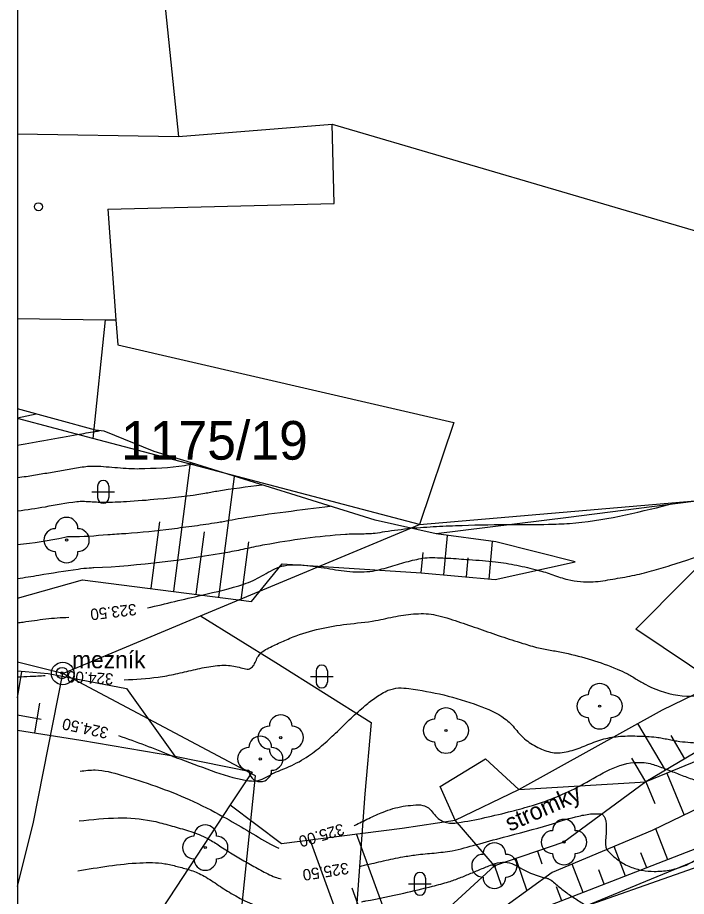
# Model space of a CAD drawing. Extents: x -564037 to -563827, y -1163561 to -1163412.
# Drawn here: x -564036.51 to -564007.08, y -1163509.03 to -1163470.35 of the extents above; entities that cross this region are included whole.
import ezdxf

# ---------------------------------------------------------------- set-up
doc = ezdxf.new("R2010")
doc.units = 0
for name, color, linetype in [('_rám PH2 a PH4', 7, 'Continuous'), ('Definiční bod kú', 7, 'Continuous'), ('Hranice parcel', 7, 'Continuous'), ('Parcelní čísla', 7, 'Continuous'), ('Vnitřní kresba', 7, 'Continuous'), ('Vrstva 14', 7, 'Continuous'), ('Vrstva 21', 7, 'Continuous'), ('Vrstva 22', 7, 'Continuous'), ('Vrstva 24', 7, 'Continuous'), ('Vrstva 25', 7, 'Continuous'), ('Vrstva 26', 7, 'Continuous'), ('Vrstva 41', 7, 'Continuous'), ('Vrstva 48', 7, 'Continuous'), ('Značky bodu BP', 7, 'Continuous'), ('Značky budov', 7, 'Continuous')]:
    doc.layers.add(name, color=color, linetype=linetype)

msp = doc.modelspace()

# ---------------------------------------------------------------- linework, layer by layer
at = {"layer": '_rám PH2 a PH4'}
msp.add_line((-564036.505, -1163412.494), (-564036.505, -1163560.994), dxfattribs=at)
at = {"layer": 'Definiční bod kú'}
msp.add_lwpolyline([(-564036.505, -1163529.976), (-564035.88, -1163528.59), (-564032.62, -1163523.46), (-564027.5, -1163518.53), (-564023.88, -1163515.79), (-564019.18, -1163512.89), (-564014.48, -1163510.5), (-564004.65, -1163507.04), (-563996.46, -1163502.51), (-563993.72, -1163500.97), (-563990.58, -1163498.69), (-563987.18, -1163495.32), (-563983.19, -1163487.81), (-563979.82, -1163480.39), (-563975.55, -1163472.37), (-563971.76, -1163466.68), (-563970.57, -1163458.32), (-563969.42, -1163449.87), (-563967.93, -1163441.99), (-563966.12, -1163434.66), (-563963.95, -1163427.04), (-563963.19, -1163422.98), (-563961.48, -1163418.93), (-563957.126, -1163412.494)], dxfattribs=at)
at = {"layer": 'Hranice parcel'}
for p, q in [((-564032.65, -1163483.65), (-564033.19, -1163488.88)), ((-564033.19, -1163488.88), (-564036.505, -1163488.003)), ((-564018.83, -1163492.67), (-564033.19, -1163488.88)), ((-564018.83, -1163492.67), (-564003.59, -1163491.36)), ((-564028.46, -1163496.69), (-564018.83, -1163492.67)), ((-564034.52, -1163499.22), (-564028.46, -1163496.69))]:
    msp.add_line(p, q, dxfattribs=at)
for points in [[(-563978.16, -1163460.35), (-563977.81, -1163470.18), (-563986.9, -1163494.46), (-563994.41, -1163501.54), (-564003.29, -1163506.07), (-564021.9, -1163513.74)], [(-564036.505, -1163475.472), (-564029.42, -1163475.59), (-564022.66, -1163475.05), (-564001.49, -1163481.27)], [(-564036.505, -1163483.596), (-564032.65, -1163483.65)], [(-564032.65, -1163483.65), (-564032.18, -1163483.66), (-564032.1, -1163484.76), (-564017.32, -1163488.18), (-564018.83, -1163492.67)], [(-564028.46, -1163496.69), (-564025.15, -1163498.74), (-564020.95, -1163501.38), (-564021.23, -1163504.52), (-564021.9, -1163513.74)], [(-564034.52, -1163499.22), (-564036.505, -1163498.716)], [(-564036.505, -1163508.595), (-564035.8, -1163505.76), (-564034.52, -1163499.22)], [(-564033.84, -1163535.6), (-564027.54, -1163518.14), (-564026.04, -1163503.72), (-564034.52, -1163499.22)]]:
    msp.add_lwpolyline(points, dxfattribs=at)
at = {"layer": 'Vnitřní kresba'}
for p, q in [((-564030.92, -1163461.24), (-564029.42, -1163475.59)), ((-564022.58, -1163478.54), (-564022.66, -1163475.05)), ((-564032.54, -1163478.78), (-564022.58, -1163478.54)), ((-564032.54, -1163478.78), (-564032.18, -1163483.66))]:
    msp.add_line(p, q, dxfattribs=at)
at = {"layer": 'Vrstva 14'}
for points in [[(-563978.09, -1163460.32), (-563977.36, -1163462.71), (-563977.84, -1163465.15), (-563976.09, -1163465.55), (-563974.34, -1163466.75), (-563974.1, -1163467.69), (-563974.4, -1163469.44), (-563976.73, -1163469.93), (-563977.88, -1163469.51), (-563978.75, -1163470.09), (-563979.22, -1163471.2), (-563981.47, -1163479.57), (-563983.82, -1163487.72), (-563987.7, -1163494.99), (-563990.79, -1163498.34), (-563994.06, -1163500.55), (-563996.65, -1163502.12), (-564005.13, -1163506.34), (-564014.58, -1163510.01)], [(-564033.08, -1163488.51), (-564036.505, -1163487.58)], [(-564032.69, -1163488.56), (-564033.08, -1163488.51)], [(-564005.7, -1163491.6), (-564006.2, -1163491.58), (-564012.27, -1163492.36), (-564018.09, -1163493.08), (-564020.78, -1163492.48), (-564028.85, -1163489.95), (-564030.49, -1163489.45), (-564032.69, -1163488.56)], [(-564027.15, -1163505), (-564024.9, -1163506.7), (-564019.59, -1163506.03), (-564017.25, -1163505.67), (-564014.46, -1163504.32), (-564008.13, -1163500.82), (-564005.74, -1163499.66), (-563997.05, -1163495.87), (-563995.48, -1163492.66)], [(-564011.97, -1163494.31), (-564015.47, -1163493.43), (-564018.09, -1163493.08)], [(-564036.505, -1163495.911), (-564033.65, -1163495.1), (-564026.22, -1163496.05), (-564024.87, -1163494.39), (-564018.75, -1163494.79), (-564015.5, -1163495.09), (-564011.97, -1163494.31)], [(-563994.18, -1163495.16), (-563996.51, -1163497.07), (-563999.3, -1163498.37), (-564001.37, -1163499.69), (-564002.8, -1163500.4), (-564008.87, -1163503.99)], [(-563993.16, -1163495.9), (-563996.19, -1163498.22), (-563998.5, -1163499.46), (-564002.25, -1163501.27), (-564008.87, -1163503.99)], [(-563991.13, -1163497.04), (-563995.37, -1163499.78), (-563998.83, -1163501.38), (-564002.12, -1163503), (-564008.59, -1163506.13), (-564012.99, -1163507.98), (-564015.01, -1163509.44), (-564017.68, -1163509.66)], [(-564036.505, -1163499.099), (-564035.16, -1163499.22), (-564031.72, -1163499.88), (-564029.59, -1163502.86)], [(-564036.505, -1163501.708), (-564033.72, -1163502.16), (-564029.59, -1163502.86), (-564026.18, -1163503.55), (-564027.15, -1163505), (-564030.15, -1163509.57), (-564034.03, -1163515.15), (-564036.505, -1163518.922)], [(-564008.87, -1163503.99), (-564012.47, -1163506.64), (-564015.53, -1163507.68), (-564017.68, -1163509.66), (-564019.48, -1163510.39), (-564022.84, -1163511.62), (-564024.26, -1163512.8), (-564027.09, -1163514.75), (-564027.62, -1163513.07), (-564028.61, -1163510.34), (-564030.15, -1163509.57)]]:
    msp.add_lwpolyline(points, dxfattribs=at)
at = {"layer": 'Vrstva 21'}
for points in [[(-564005.74, -1163499.66), (-564009.31, -1163497.27), (-564004.92, -1163492.86)], [(-564017.25, -1163505.67), (-564017.92, -1163504.2), (-564015.92, -1163502.97), (-564014.46, -1163504.32)], [(-564014.46, -1163504.32), (-564008.87, -1163503.99)], [(-564015.53, -1163507.68), (-564017.25, -1163505.67)]]:
    msp.add_lwpolyline(points, dxfattribs=at)
at = {"layer": 'Vrstva 22'}
for centre in [(-564034.35, -1163493.35), (-564010.9, -1163500.66), (-564017.66, -1163501.73), (-564024.93, -1163502.04), (-564025.83, -1163502.98), (-564012.47, -1163506.64), (-564028.25, -1163506.88), (-564015.53, -1163507.68)]:
    msp.add_circle(centre, 0.05, dxfattribs=at)
for centre, start, end in [((-564034.35, -1163492.85), 0, 180), ((-564034.85, -1163493.35), 90, 270), ((-564033.85, -1163493.35), 270, 90), ((-564034.35, -1163493.85), 180, 0), ((-564010.9, -1163500.16), 0, 180), ((-564011.4, -1163500.66), 90, 270), ((-564010.4, -1163500.66), 270, 90), ((-564017.66, -1163501.23), 0, 180), ((-564024.93, -1163501.54), 0, 180), ((-564010.9, -1163501.16), 180, 0), ((-564025.43, -1163502.04), 90, 270), ((-564024.43, -1163502.04), 270, 90), ((-564018.16, -1163501.73), 90, 270), ((-564017.16, -1163501.73), 270, 90), ((-564025.83, -1163502.48), 0, 180), ((-564017.66, -1163502.23), 180, 0), ((-564026.33, -1163502.98), 90, 270), ((-564024.93, -1163502.54), 180, 0), ((-564025.33, -1163502.98), 270, 90), ((-564025.83, -1163503.48), 180, 0), ((-564012.47, -1163506.14), 0, 180), ((-564028.25, -1163506.38), 0, 180), ((-564012.97, -1163506.64), 90, 270), ((-564011.97, -1163506.64), 270, 90), ((-564028.75, -1163506.88), 90, 270), ((-564027.75, -1163506.88), 270, 90), ((-564015.53, -1163507.18), 0, 180), ((-564016.03, -1163507.68), 90, 270), ((-564015.03, -1163507.68), 270, 90), ((-564012.47, -1163507.14), 180, 0), ((-564028.25, -1163507.38), 180, 0), ((-564015.53, -1163508.18), 180, 0)]:
    msp.add_arc(centre, 0.5, start, end, dxfattribs=at)
at = {"layer": 'Vrstva 24'}
for radius in [0.25, 0.05]:
    msp.add_circle((-564034.55, -1163499.2), radius, dxfattribs=at)
for points in [[(-564036.505, -1163489.167), (-564033.879, -1163488.703), (-564033.095, -1163488.569), (-564032.88, -1163488.53)], [(-564036.505, -1163492.065), (-564035.281, -1163491.88), (-564033.905, -1163491.655), (-564033.758, -1163491.643), (-564033.493, -1163491.646), (-564033.227, -1163491.66), (-564032.962, -1163491.675), (-564032.696, -1163491.679), (-564031.72, -1163491.649), (-564030.331, -1163491.539), (-564028.273, -1163491.289), (-564028.139, -1163491.265), (-564028.006, -1163491.238), (-564027.738, -1163491.19), (-564025.74, -1163490.92)], [(-564036.505, -1163495.045), (-564035.565, -1163494.892), (-564033.841, -1163494.623), (-564033.354, -1163494.57), (-564033.147, -1163494.56), (-564027.164, -1163493.861), (-564026.778, -1163493.789), (-564026.394, -1163493.706), (-564026.01, -1163493.622), (-564025.624, -1163493.548), (-564022.084, -1163493.089), (-564021.758, -1163493.072), (-564021.43, -1163493.069), (-564021.103, -1163493.064), (-564020.777, -1163493.039), (-564020.345, -1163492.975), (-564019.205, -1163492.831), (-564018.079, -1163492.749), (-564016.953, -1163492.702), (-564014.698, -1163492.66), (-564013.156, -1163492.656), (-564012.231, -1163492.615), (-564007.86, -1163491.79)], [(-564031.812, -1163499.5), (-564030.324, -1163499.377), (-564029.547, -1163499.242), (-564028.773, -1163499.061), (-564028.001, -1163498.908), (-564027.615, -1163498.867), (-564027.23, -1163498.862), (-564026.607, -1163498.989), (-564026.346, -1163499.024), (-564026.173, -1163498.931), (-564026.053, -1163498.733), (-564025.945, -1163498.506), (-564025.804, -1163498.324), (-564025.519, -1163498.129), (-564024.955, -1163497.86), (-564024.387, -1163497.614), (-564023.213, -1163497.254), (-564022.022, -1163497.051), (-564020.757, -1163496.892), (-564019.862, -1163496.708), (-564018.98, -1163496.594), (-564018.537, -1163496.592), (-564018.102, -1163496.651), (-564017.139, -1163496.933), (-564016.188, -1163497.257), (-564015.239, -1163497.589), (-564014.283, -1163497.894), (-564013.587, -1163498.092), (-564013.3, -1163498.155), (-564013.009, -1163498.205), (-564012.719, -1163498.253), (-564012.43, -1163498.312), (-564010.133, -1163499.025), (-564009.7, -1163499.224), (-564009.288, -1163499.466), (-564008.873, -1163499.71), (-564008.431, -1163499.916), (-564006.88, -1163500.213), (-564005.699, -1163500.108), (-564005.367, -1163500.004), (-564005.352, -1163499.957), (-564005.385, -1163499.904), (-564005.432, -1163499.847), (-564005.458, -1163499.79), (-564005.454, -1163499.732), (-564005.373, -1163499.663), (-564004.291, -1163498.6), (-564003.237, -1163497.506), (-564002.153, -1163496.417), (-564001.583, -1163495.886), (-564000.985, -1163495.371), (-564000.543, -1163495.196), (-564000.072, -1163495.171), (-563999.593, -1163495.223), (-563999.117, -1163495.267), (-563998.655, -1163495.218), (-563997.978, -1163494.98), (-563997.317, -1163494.68), (-563996.656, -1163494.38), (-563995.98, -1163494.14), (-563995.697, -1163494.069), (-563995.41, -1163494.016), (-563995.123, -1163493.963), (-563994.84, -1163493.89), (-563994.137, -1163493.61)], [(-564036.505, -1163499.371), (-564035.955, -1163499.345), (-564035.287, -1163499.307)], [(-564033.86, -1163507.91), (-564031.122, -1163507.553), (-564030.032, -1163507.592), (-564029.488, -1163507.711), (-564028.944, -1163507.863), (-564028.376, -1163508.095), (-564028.052, -1163508.286), (-564027.739, -1163508.492), (-564027.427, -1163508.7), (-564027.104, -1163508.896), (-564025.446, -1163509.596), (-564024.844, -1163509.663)], [(-564021.371, -1163509.263), (-564021.186, -1163509.229), (-564019.518, -1163508.884), (-564018.247, -1163508.582), (-564017.543, -1163508.388), (-564017.047, -1163508.212), (-564016.56, -1163508.013), (-564016.075, -1163507.809), (-564015.585, -1163507.616), (-564015.501, -1163507.589), (-564015.062, -1163507.521), (-564014.301, -1163507.825), (-564013.306, -1163508.208), (-564013.192, -1163508.237), (-564013.152, -1163508.254), (-564012.927, -1163508.404), (-564012.718, -1163508.577), (-564012.293, -1163508.914), (-564011.825, -1163509.22), (-564011.356, -1163509.532), (-564010.401, -1163510.124), (-564008.351, -1163510.852), (-564006.535, -1163511.003), (-564002.621, -1163511.374), (-564001.777, -1163511.54), (-564000.952, -1163511.799), (-564000.128, -1163512.073), (-563999.289, -1163512.284), (-563996.174, -1163512.66), (-563990.953, -1163512.711), (-563989.709, -1163512.624), (-563988.468, -1163512.494), (-563986.004, -1163512.066), (-563985.116, -1163511.837), (-563984.242, -1163511.579), (-563983.382, -1163511.285), (-563982.536, -1163510.951), (-563981.471, -1163510.495)]]:
    msp.add_spline(points, degree=3, dxfattribs=at)
at = {"layer": 'Vrstva 25'}
for p, q in [((-564032.986, -1163490.976), (-564032.986, -1163491.476)), ((-564032.486, -1163490.976), (-564032.486, -1163491.476)), ((-564033.236, -1163491.226), (-564032.236, -1163491.226)), ((-564023.376, -1163499.106), (-564023.376, -1163499.606)), ((-564022.876, -1163499.106), (-564022.876, -1163499.606)), ((-564023.626, -1163499.356), (-564022.626, -1163499.356)), ((-564019.306, -1163508.476), (-564018.306, -1163508.476)), ((-564019.056, -1163508.226), (-564019.056, -1163508.726)), ((-564018.556, -1163508.226), (-564018.556, -1163508.726))]:
    msp.add_line(p, q, dxfattribs=at)
for centre, start, end in [((-564032.736, -1163490.976), 0, 180), ((-564032.736, -1163491.476), 180, 0), ((-564023.126, -1163499.106), 0, 180), ((-564023.126, -1163499.606), 180, 0), ((-564018.806, -1163508.226), 0, 180), ((-564018.806, -1163508.726), 180, 0)]:
    msp.add_arc(centre, 0.25, start, end, dxfattribs=at)
for points in [[(-564021.704, -1163505.921), (-564021.679, -1163505.908), (-564021.057, -1163505.601), (-564020.425, -1163505.318), (-564019.55, -1163505.067), (-564019.102, -1163505.015), (-564018.672, -1163505.024), (-564018.428, -1163505.139), (-564018.218, -1163505.363), (-564018.005, -1163505.598), (-564017.748, -1163505.747), (-564017.265, -1163505.807), (-564017.147, -1163505.791), (-564014.765, -1163505.278), (-564013.855, -1163505.025), (-564011.755, -1163504.16), (-564009.388, -1163503.14), (-564008.683, -1163503.187), (-564008.113, -1163503.379), (-564007.551, -1163503.598), (-564006.987, -1163503.811), (-564006.412, -1163503.982), (-564005.323, -1163504.224), (-564003.629, -1163504.674), (-564003.259, -1163504.818), (-564002.04, -1163505.119), (-564001.419, -1163505.147), (-564000.82, -1163505.047), (-564000.232, -1163504.846), (-563999.668, -1163504.61), (-563998.596, -1163504.017), (-563996.597, -1163502.522), (-563996.542, -1163502.471), (-563996.497, -1163502.435), (-563996.203, -1163502.3), (-563995.993, -1163502.248), (-563990.872, -1163502.073), (-563988.998, -1163502), (-563988.338, -1163501.889), (-563985.154, -1163501.005), (-563982.47, -1163500.199)], [(-564033.75, -1163503.52), (-564033.09, -1163503.468), (-564031.943, -1163503.693), (-564028.953, -1163504.771), (-564027.455, -1163505.522), (-564026.417, -1163506.121), (-564025.381, -1163506.726), (-564025.017, -1163506.915)]]:
    msp.add_spline(points, degree=3, dxfattribs=at)
at = {"layer": 'Vrstva 26'}
for p, q in [((-564036.505, -1163487.967), (-564035.69, -1163487.8)), ((-564036.505, -1163501.036), (-564035.461, -1163501.229))]:
    msp.add_line(p, q, dxfattribs=at)
for points in [[(-564030.787, -1163496.336), (-564028.401, -1163495.771), (-564026.55, -1163495.284), (-564026.147, -1163495.128), (-564025.763, -1163494.926), (-564025.381, -1163494.714), (-564024.983, -1163494.529), (-564024.778, -1163494.476), (-564023.777, -1163494.469), (-564022.768, -1163494.613), (-564021.761, -1163494.742), (-564020.768, -1163494.69), (-564020.378, -1163494.594), (-564019.992, -1163494.479), (-564019.605, -1163494.362), (-564019.215, -1163494.261), (-564018.494, -1163494.127), (-564018.03, -1163494.125), (-564017.565, -1163494.144), (-564016.635, -1163494.209), (-564015.486, -1163494.302), (-564014.546, -1163494.457), (-564013.618, -1163494.674), (-564013.287, -1163494.768), (-564012.961, -1163494.879), (-564012.635, -1163494.991), (-564012.302, -1163495.087), (-564011.185, -1163495.184), (-564010.325, -1163495.07), (-564009.466, -1163494.913), (-564008.615, -1163494.71), (-564007.775, -1163494.461), (-564005.875, -1163493.819), (-564004.998, -1163493.505), (-564003.872, -1163493.237), (-564002.608, -1163493.074), (-563997.404, -1163492.441), (-563996.84, -1163492.35), (-563996.277, -1163492.238), (-563995.433, -1163492.101), (-563995.293, -1163492.088), (-563995.152, -1163492.08), (-563994.744, -1163492.153), (-563994.067, -1163492.223), (-563993.74, -1163492.055), (-563993.078, -1163491.408), (-563992.901, -1163491.103), (-563992.782, -1163490.74), (-563992.679, -1163490.374), (-563992.526, -1163489.633), (-563992.48, -1163489.295), (-563992.41, -1163488.908)], [(-564036.505, -1163490.599), (-564036.127, -1163490.545), (-564035.471, -1163490.44), (-564034.816, -1163490.328), (-564034.16, -1163490.216), (-564033.5, -1163490.11), (-564033.221, -1163490.093), (-564032.726, -1163490.111), (-564032.23, -1163490.15), (-564031.735, -1163490.189), (-564031.239, -1163490.207), (-564030.908, -1163490.198), (-564028.91, -1163490.014), (-564028.829, -1163490), (-564028.806, -1163489.999), (-564028.73, -1163489.99)], [(-564036.505, -1163493.545), (-564034.433, -1163493.218), (-564034.309, -1163493.194), (-564034.195, -1163493.193), (-564032.535, -1163493.106), (-564031.742, -1163493.053), (-564029.726, -1163492.85), (-564028.722, -1163492.719), (-564027.719, -1163492.573), (-564027.456, -1163492.528), (-564027.193, -1163492.477), (-564026.667, -1163492.385), (-564022.75, -1163491.86)], [(-564036.505, -1163496.989), (-564036.266, -1163496.955), (-564035.262, -1163496.821), (-564034.254, -1163496.749), (-564034.245, -1163496.749)], [(-564032.062, -1163501.954), (-564029.752, -1163502.832), (-564029.575, -1163502.905), (-564029.515, -1163502.926), (-564026.43, -1163503.924), (-564026.019, -1163503.946), (-564025.314, -1163503.643), (-564024.556, -1163503.317), (-564023.709, -1163502.848), (-564023.05, -1163502.337), (-564022.439, -1163501.769), (-564021.838, -1163501.188), (-564021.209, -1163500.632), (-564020.733, -1163500.262), (-564020.476, -1163500.101), (-564020.197, -1163499.959), (-564019.747, -1163499.857), (-564019.293, -1163499.886), (-564017.758, -1163500.167), (-564016.239, -1163500.626), (-564015.064, -1163501.212), (-564014.816, -1163501.423), (-564014.602, -1163501.669), (-564014.388, -1163501.92), (-564014.134, -1163502.148), (-564013.542, -1163502.512), (-564013.225, -1163502.636), (-564012.894, -1163502.71), (-564012.546, -1163502.699), (-564012.199, -1163502.629), (-564011.502, -1163502.387), (-564010.8, -1163502.128), (-564010.087, -1163501.994), (-564009.248, -1163501.973), (-564008.411, -1163502.024), (-564008.151, -1163502.065), (-564007.892, -1163502.117), (-564007.634, -1163502.17), (-564007.375, -1163502.21), (-564006.906, -1163502.255), (-564006.434, -1163502.283), (-564005.962, -1163502.314), (-564005.493, -1163502.369), (-564003.875, -1163502.725), (-564003.078, -1163502.948), (-564002.283, -1163503.18), (-564002.242, -1163503.195), (-564001.98, -1163503.221), (-564001.075, -1163502.909), (-563999.457, -1163502.404), (-563998.647, -1163502.146), (-563998.242, -1163502.005), (-563998.039, -1163501.944), (-563997.939, -1163501.907), (-563997.838, -1163501.853), (-563997.785, -1163501.735), (-563998.108, -1163501.124), (-563998.377, -1163500.842), (-563998.693, -1163500.582), (-563999.025, -1163500.42), (-563999.386, -1163500.375), (-564000.04, -1163500.575), (-564000.222, -1163500.738), (-564000.381, -1163500.936), (-564000.542, -1163501.14), (-564000.728, -1163501.319), (-564001.452, -1163501.831), (-564001.829, -1163502.005), (-564002.013, -1163502.045), (-564002.192, -1163502.046), (-564002.617, -1163501.879), (-564003.007, -1163501.538), (-564003.361, -1163501.092), (-564003.68, -1163500.611), (-564003.715, -1163500.54)], [(-564021.468, -1163507.71), (-564021.242, -1163507.658), (-564020.402, -1163507.466), (-564019.558, -1163507.292), (-564018.974, -1163507.201), (-564018.579, -1163507.155), (-564018.183, -1163507.121), (-564017.395, -1163507.019), (-564016.324, -1163506.752), (-564015.131, -1163506.427), (-564013.124, -1163505.877), (-564011.958, -1163505.53), (-564011.372, -1163505.413), (-564011.082, -1163505.393), (-564010.939, -1163505.396), (-564010.796, -1163505.408), (-564010.707, -1163505.514), (-564010.652, -1163505.629), (-564010.617, -1163505.879), (-564010.626, -1163506.398), (-564010.641, -1163506.685), (-564010.632, -1163506.828), (-564010.586, -1163506.969), (-564010.46, -1163507.105), (-564010.333, -1163507.228), (-564010.076, -1163507.438), (-564009.553, -1163507.731), (-564009.025, -1163507.883), (-564008.499, -1163507.928), (-564007.844, -1163507.876), (-564007.186, -1163507.69), (-564006.53, -1163507.33), (-564006.203, -1163507.072), (-564006.04, -1163506.922), (-564005.877, -1163506.757), (-564005.786, -1163506.529), (-564005.801, -1163506.299), (-564005.847, -1163506.162), (-564005.934, -1163506.015), (-564005.993, -1163505.892), (-564005.951, -1163505.824), (-564005.87, -1163505.816), (-564005.789, -1163505.826), (-564005.625, -1163505.887), (-564005.294, -1163506.039), (-564005.154, -1163506.08), (-564004.954, -1163506.144), (-564004.272, -1163506.437), (-563998.752, -1163508.301), (-563998.369, -1163508.389), (-563996.721, -1163508.55), (-563995.072, -1163508.639), (-563991.772, -1163508.696), (-563989.868, -1163508.644), (-563988.87, -1163508.516), (-563987.881, -1163508.343), (-563985.925, -1163507.884), (-563984.065, -1163507.363)], [(-564033.8, -1163505.71), (-564032.074, -1163505.577), (-564030.613, -1163505.702), (-564029.889, -1163505.883), (-564029.168, -1163506.088), (-564028.429, -1163506.344), (-564028.048, -1163506.535), (-564027.562, -1163506.843), (-564026.408, -1163507.544), (-564025.812, -1163507.873), (-564025.179, -1163508.182), (-564024.906, -1163508.265)]]:
    msp.add_spline(points, degree=3, dxfattribs=at)
at = {"layer": 'Vrstva 48'}
for p, q in [((-564029.638, -1163495.6), (-564028.895, -1163489.936)), ((-564027.655, -1163495.86), (-564026.958, -1163490.546)), ((-564030.63, -1163495.47), (-564030.247, -1163492.55)), ((-564028.647, -1163495.73), (-564028.287, -1163492.986)), ((-564026.664, -1163495.99), (-564026.327, -1163493.421)), ((-564017.754, -1163494.882), (-564017.594, -1163493.146)), ((-564015.763, -1163495.066), (-564015.61, -1163493.411)), ((-564018.75, -1163494.79), (-564018.668, -1163493.902)), ((-564016.758, -1163494.974), (-564016.68, -1163494.126)), ((-564036.505, -1163500.289), (-564036.318, -1163499.128)), ((-564035.741, -1163501.829), (-564035.531, -1163500.525)), ((-564008.009, -1163503.482), (-564009.224, -1163501.422)), ((-564007.147, -1163502.974), (-564007.747, -1163501.956)), ((-564008.87, -1163503.99), (-564009.485, -1163502.948)), ((-564007.945, -1163503.61), (-564007.189, -1163505.452)), ((-564008.87, -1163503.99), (-564008.48, -1163504.939)), ((-564007.897, -1163507.415), (-564008.422, -1163506.059)), ((-564021.901, -1163511.276), (-564023.635, -1163506.54)), ((-564020.023, -1163510.589), (-564021.599, -1163506.283)), ((-564009.762, -1163508.137), (-564010.266, -1163506.835)), ((-564014.584, -1163507.357), (-564014.098, -1163508.781)), ((-564013.637, -1163507.034), (-564013.444, -1163507.601)), ((-564008.83, -1163507.776), (-564009.087, -1163507.111)), ((-564015.53, -1163507.68), (-564015.238, -1163508.537)), ((-564011.627, -1163508.859), (-564012.111, -1163507.61)), ((-564010.695, -1163508.498), (-564010.942, -1163507.86)), ((-564020.962, -1163510.932), (-564021.789, -1163508.672)), ((-564012.56, -1163509.22), (-564012.797, -1163508.609))]:
    msp.add_line(p, q, dxfattribs=at)
at = {"layer": 'Značky bodu BP'}
for radius in [0.5, 0.0303]:
    msp.add_circle((-564034.52, -1163499.22), radius, dxfattribs=at)
at = {"layer": 'Značky budov'}
msp.add_circle((-564035.587, -1163478.679), 0.175, dxfattribs=at)

# ---------------------------------------------------------------- texts
at = {"layer": 'Parcelní čísla'}
msp.add_text('1175/19', height=1.7, dxfattribs=at).set_placement((-564031.956, -1163489.81))
at = {"layer": 'Vrstva 25'}
for s, rotation, p in [('323.50', 186.8068, (-564031.301, -1163496.146)), ('324.00', 176.826, (-564032.276, -1163499.221)), ('324.50', 167.8359, (-564032.476, -1163501.613)), ('325.00', 196.6676, (-564022.223, -1163505.814)), ('325.50', 188.943, (-564021.978, -1163507.538))]:
    msp.add_text(s, height=0.5, rotation=rotation, dxfattribs=at).set_placement(p)
at = {"layer": 'Vrstva 41'}
msp.add_text('mezník', height=0.75, dxfattribs=at).set_placement((-564034.11, -1163498.99))
msp.add_text('stromky', height=0.75, rotation=23.9211, dxfattribs=at).set_placement((-564014.85, -1163506.19))

doc.saveas('drawing.dxf')
